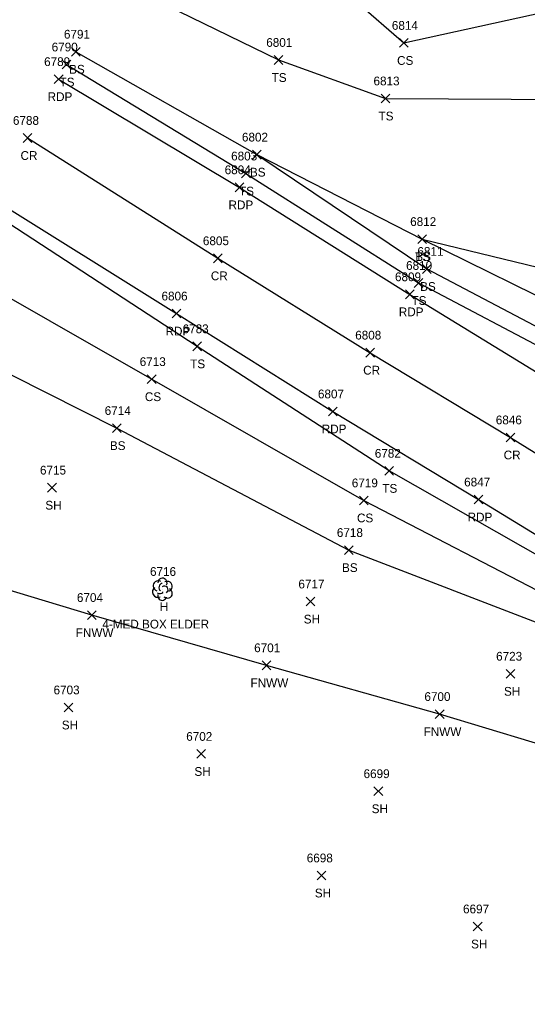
# Model space of a CAD drawing. Extents: x 1505656 to 1508446, y 700805 to 703031.
# Drawn here: x 1507222.6 to 1507338.7, y 701219.6 to 701441 of the extents above; entities that cross this region are included whole.
import ezdxf

# ---------------------------------------------------------------- set-up
doc = ezdxf.new("R2010")
doc.units = 0
for name, color, linetype in [('L_A', 7, 'Continuous'), ('L_C', 7, 'Continuous'), ('L_I', 7, 'Continuous'), ('L_TIC', 7, 'Continuous'), ('LELB', 7, 'Continuous'), ('LFNC', 7, 'Continuous'), ('LTD', 7, 'Continuous'), ('P_A', 7, 'Continuous'), ('P_I', 7, 'Continuous'), ('P_TIC', 7, 'Continuous'), ('PET', 7, 'Continuous'), ('PRC', 7, 'Continuous')]:
    doc.layers.add(name, color=color, linetype=linetype)

msp = doc.modelspace()

# ---------------------------------------------------------------- linework, layer by layer
at = {"layer": 'L_TIC'}
for points in [[(1507309.43, 701434.66), (1507311.43, 701436.66)], [(1507311.43, 701434.66), (1507309.43, 701436.66)], [(1507234.56, 701432.65), (1507236.56, 701434.65)], [(1507236.56, 701432.65), (1507234.56, 701434.65)], [(1507280.83, 701430.77), (1507282.83, 701432.77)], [(1507282.83, 701430.77), (1507280.83, 701432.77)], [(1507232.42, 701429.73), (1507234.42, 701431.73)], [(1507234.42, 701429.73), (1507232.42, 701431.73)], [(1507305.24, 701421.98), (1507307.24, 701423.98)], [(1507307.24, 701421.98), (1507305.24, 701423.98)], [(1507275.85, 701409.17), (1507277.85, 701411.17)], [(1507277.85, 701409.17), (1507275.85, 701411.17)], [(1507275.85, 701409.17), (1507277.85, 701411.17)], [(1507277.85, 701409.17), (1507275.85, 701411.17)], [(1507273.38, 701404.85), (1507275.38, 701406.85)], [(1507275.38, 701404.85), (1507273.38, 701406.85)], [(1507313.61, 701389.89), (1507315.61, 701391.89)], [(1507315.61, 701389.89), (1507313.61, 701391.89)], [(1507313.61, 701389.89), (1507315.61, 701391.89)], [(1507315.61, 701389.89), (1507313.61, 701391.89)], [(1507314.69, 701383.08), (1507316.69, 701385.08)], [(1507316.69, 701383.08), (1507314.69, 701385.08)], [(1507312.77, 701379.88), (1507314.77, 701381.88)], [(1507314.77, 701379.88), (1507312.77, 701381.88)], [(1507262.23, 701365.42), (1507264.23, 701367.42)], [(1507264.23, 701365.42), (1507262.23, 701367.42)], [(1507251.86, 701357.93), (1507253.86, 701359.93)], [(1507253.86, 701357.93), (1507251.86, 701359.93)], [(1507243.87, 701346.76), (1507245.87, 701348.76)], [(1507245.87, 701346.76), (1507243.87, 701348.76)], [(1507306.1, 701337.01), (1507308.1, 701339.01)], [(1507308.1, 701337.01), (1507306.1, 701339.01)], [(1507229.09, 701333.17), (1507231.09, 701335.17)], [(1507231.09, 701333.17), (1507229.09, 701335.17)], [(1507300.28, 701330.26), (1507302.28, 701332.26)], [(1507302.28, 701330.26), (1507300.28, 701332.26)], [(1507296.87, 701318.93), (1507298.87, 701320.93)], [(1507298.87, 701318.93), (1507296.87, 701320.93)], [(1507288.09, 701307.18), (1507290.09, 701309.18)], [(1507290.09, 701307.18), (1507288.09, 701309.18)], [(1507238.17, 701304.1), (1507240.17, 701306.1)], [(1507240.17, 701304.1), (1507238.17, 701306.1)], [(1507278.07, 701292.63), (1507280.07, 701294.63)], [(1507280.07, 701292.63), (1507278.07, 701294.63)], [(1507333.8, 701290.7), (1507335.8, 701292.7)], [(1507335.8, 701290.7), (1507333.8, 701292.7)], [(1507232.84, 701283.01), (1507234.84, 701285.01)], [(1507234.84, 701283.01), (1507232.84, 701285.01)], [(1507317.6, 701281.5), (1507319.6, 701283.5)], [(1507319.6, 701281.5), (1507317.6, 701283.5)], [(1507263.13, 701272.41), (1507265.13, 701274.41)], [(1507265.13, 701272.41), (1507263.13, 701274.41)], [(1507303.6, 701263.9), (1507305.6, 701265.9)], [(1507305.6, 701263.9), (1507303.6, 701265.9)], [(1507290.61, 701244.67), (1507292.61, 701246.67)], [(1507292.61, 701244.67), (1507290.61, 701246.67)], [(1507326.29, 701233.03), (1507328.29, 701235.03)], [(1507328.29, 701233.03), (1507326.29, 701235.03)]]:
    msp.add_lwpolyline(points, dxfattribs=at)
at = {"layer": 'LELB'}
for points in [[(1507253.51, 701468.63), (1507288.66, 701454.6), (1507310.43, 701435.66), (1507348.27, 701444), (1507370.84, 701446.3), (1507401.59, 701448.68)], [(1507244.77, 701449.89), (1507281.83, 701431.77), (1507306.24, 701422.98), (1507349.34, 701422.75), (1507389.23, 701429.14), (1507420.95, 701414.98), (1507446.82, 701397.27), (1507479.15, 701378.11), (1507493.85, 701367.81), (1507514.9, 701342.52), (1507491.37, 701327.79), (1507458.66, 701337.87), (1507423.97, 701348.78), (1507386.76, 701365.39), (1507354.41, 701381.26)], [(1507235.56, 701433.65), (1507276.85, 701410.17), (1507315.69, 701384.08), (1507347.33, 701367.45), (1507378.23, 701346.54), (1507406.05, 701333.56), (1507432.55, 701320.24), (1507465.52, 701310.91), (1507482.03, 701304.93), (1507508.08, 701304.28), (1507527, 701309.32), (1507530.54, 701311.37), (1507534.33, 701313.25), (1507542.53, 701316.02)], [(1507233.42, 701430.73), (1507274.38, 701405.85), (1507313.77, 701380.88), (1507345.78, 701364.01), (1507376.65, 701344.28), (1507403.21, 701328.51), (1507429.39, 701315.22), (1507462.05, 701305), (1507481.51, 701300.2), (1507509.4, 701297.47), (1507533.93, 701303.18), (1507548.93, 701313.82)], [(1507276.85, 701410.17), (1507314.61, 701390.89), (1507350.47, 701373.21), (1507382.29, 701350.94), (1507409.06, 701339.05), (1507436.21, 701326.88), (1507468.39, 701316.49), (1507482.66, 701312.29), (1507508.07, 701310.82), (1507524.68, 701314.62), (1507530.84, 701315.71), (1507533.71, 701315.69), (1507538.02, 701318.49)], [(1507664.64, 701288.76), (1507647.23, 701299.02), (1507624.46, 701303.4), (1507602.75, 701298.73), (1507589.52, 701290.79), (1507567.73, 701274.99), (1507546.1, 701263.56), (1507532.57, 701260.5), (1507511.15, 701257.25), (1507494.82, 701257.14), (1507477.93, 701258.45), (1507454.88, 701263), (1507442.63, 701266.73), (1507416.76, 701276.5), (1507380.5, 701295.43), (1507349.66, 701313.74), (1507307.1, 701338.01), (1507263.23, 701366.42), (1507214.44, 701398.2)], [(1507314.61, 701390.89), (1507354.41, 701381.26)], [(1507206.22, 701385.53), (1507252.86, 701358.93), (1507301.28, 701331.26), (1507345.08, 701308.55), (1507379.28, 701292.34), (1507415.34, 701274.6), (1507442.69, 701262.41), (1507477.36, 701252.75), (1507504.09, 701250.04), (1507524.24, 701244.68), (1507543.71, 701240.05), (1507564.82, 701236.64), (1507598.94, 701231.93), (1507652.74, 701217.67)], [(1507196.76, 701372), (1507244.87, 701347.76), (1507297.87, 701319.93), (1507344.77, 701301.89), (1507376.8, 701287.99), (1507414.57, 701272.26), (1507441.62, 701260.06), (1507475.85, 701242.93), (1507502.94, 701235.06), (1507524.76, 701229.88), (1507541.19, 701229.88), (1507544.67, 701227.39), (1507563.69, 701226.67), (1507597.85, 701222.6), (1507649.46, 701209.48)]]:
    msp.add_lwpolyline(points, dxfattribs=at)
at = {"layer": 'LFNC'}
msp.add_lwpolyline([(1507721.58, 701162.07), (1507708.46, 701169.26), (1507682.76, 701176.46), (1507629.63, 701192.11), (1507592.19, 701203.04), (1507562.07, 701211.89), (1507541.96, 701217.44), (1507530.4, 701220.69), (1507490.47, 701232.17), (1507463.39, 701240.21), (1507439.34, 701246.9), (1507401.64, 701257.79), (1507360.86, 701269.69), (1507318.6, 701282.5), (1507279.07, 701293.63), (1507239.17, 701305.1), (1507200.8, 701316.65)], dxfattribs=at)
at = {"layer": 'LTD'}
msp.add_line((1507255.27, 701311.04), (1507255.27, 701311.04), dxfattribs=at)
msp.add_line((1507255.27, 701311.04), (1507255.27, 701311.04), dxfattribs=at)
msp.add_arc((1507255.31, 701312.47), 1.05, 335.5272, 180.9563, dxfattribs=at)
for centre, major_axis, ratio, start_param, end_param in [((1507254.48, 701311.7), (1.21, -0.51), 0.895232, 1.570796, 4.712389), ((1507256.31, 701311.62), (-1.14, -0.48), 0.949671, 1.570796, 4.712389), ((1507254.18, 701310.33), (0.58, -1.04), 0.959034, 3.141593, 6.283185), ((1507254.81, 701310.29), (-0.625, -0.083), 0.423636, 0, 3.141593), ((1507255.06, 701311.5), (-0.208, -0.792), 0.645439, 3.141593, 6.283185), ((1507255.77, 701310.87), (-0.5, 0.667), 0.989748, 3.141593, 6.283185), ((1507256.27, 701310.2), (-1.09, 0.79), 0.841452, 1.570796, 4.712389), ((1507255.27, 701309.54), (0.26, 1.06), 0.942809, 1.570796, 4.712389)]:
    msp.add_ellipse(centre, major_axis=major_axis, ratio=ratio, start_param=start_param, end_param=end_param, dxfattribs=at)
at = {"layer": 'P_TIC'}
for points in [[(1507230.61, 701426.39), (1507232.61, 701428.39)], [(1507232.61, 701426.39), (1507230.61, 701428.39)], [(1507223.48, 701412.97), (1507225.48, 701414.97)], [(1507225.48, 701412.97), (1507223.48, 701414.97)], [(1507271.91, 701401.71), (1507273.91, 701403.71)], [(1507273.91, 701401.71), (1507271.91, 701403.71)], [(1507266.93, 701385.51), (1507268.93, 701387.51)], [(1507268.93, 701385.51), (1507266.93, 701387.51)], [(1507310.8, 701377.29), (1507312.8, 701379.29)], [(1507312.8, 701377.29), (1507310.8, 701379.29)], [(1507257.54, 701372.9), (1507259.54, 701374.9)], [(1507259.54, 701372.9), (1507257.54, 701374.9)], [(1507301.71, 701363.98), (1507303.71, 701365.98)], [(1507303.71, 701363.98), (1507301.71, 701365.98)], [(1507293.19, 701350.56), (1507295.19, 701352.56)], [(1507295.19, 701350.56), (1507293.19, 701352.56)], [(1507333.78, 701344.63), (1507335.78, 701346.63)], [(1507335.78, 701344.63), (1507333.78, 701346.63)], [(1507326.49, 701330.46), (1507328.49, 701332.46)], [(1507328.49, 701330.46), (1507326.49, 701332.46)]]:
    msp.add_lwpolyline(points, dxfattribs=at)
at = {"layer": 'PET'}
for points in [[(1507231.61, 701427.39), (1507272.91, 701402.71), (1507311.8, 701378.29), (1507343.21, 701359.04), (1507374.88, 701340.26), (1507401.32, 701325.13), (1507427.17, 701310.75), (1507459.87, 701298.7), (1507480.09, 701294.48), (1507509.29, 701293.36), (1507525.83, 701296.14), (1507540.02, 701301.61), (1507551.73, 701310.36)], [(1507215.48, 701400.74), (1507258.54, 701373.9), (1507294.19, 701351.56), (1507327.49, 701331.46), (1507359.99, 701311.61), (1507385.1, 701296.57), (1507413.33, 701281.68), (1507446.05, 701268.76), (1507474.38, 701261.9), (1507510.64, 701260.64), (1507538.44, 701265.38), (1507556.26, 701273.11), (1507573.81, 701284.3)]]:
    msp.add_lwpolyline(points, dxfattribs=at)
at = {"layer": 'PRC'}
msp.add_lwpolyline([(1507224.48, 701413.97), (1507267.93, 701386.51), (1507302.71, 701364.98), (1507334.78, 701345.63), (1507366.2, 701326.16), (1507393.17, 701310.52), (1507419.83, 701295.27), (1507450.97, 701283.62), (1507477.64, 701277.69), (1507509.18, 701276.82), (1507530.27, 701280.07), (1507548.96, 701287.59), (1507564.92, 701299.3)], dxfattribs=at)

# ---------------------------------------------------------------- texts
at = {"layer": 'L_A'}
for s, p in [('CS', (1507308.88, 701430.66)), ('BS', (1507234, 701428.65)), ('TS', (1507231.82, 701425.73)), ('TS', (1507280.24, 701426.77)), ('TS', (1507304.65, 701417.98)), ('BS', (1507275.29, 701405.17)), ('BS', (1507275.29, 701405.17)), ('TS', (1507272.79, 701400.85)), ('TS', (1507313.01, 701385.89)), ('BS', (1507313.05, 701385.89)), ('BS', (1507314.14, 701379.08)), ('TS', (1507312.18, 701375.88)), ('TS', (1507261.64, 701361.42)), ('CS', (1507251.3, 701353.93)), ('BS', (1507243.31, 701342.76)), ('TS', (1507305.51, 701333.01)), ('SH', (1507228.57, 701329.17)), ('CS', (1507299.73, 701326.26)), ('BS', (1507296.31, 701314.93)), ('H', (1507254.7, 701306.04)), ('SH', (1507287.57, 701303.18)), ('FNWW', (1507235.52, 701300.1)), ('FNWW', (1507275.42, 701288.63)), ('SH', (1507333.28, 701286.7)), ('SH', (1507232.33, 701279.01)), ('FNWW', (1507314.94, 701277.5)), ('SH', (1507262.61, 701268.41)), ('SH', (1507303.08, 701259.9)), ('SH', (1507290.1, 701240.67)), ('SH', (1507325.78, 701229.03))]:
    msp.add_text(s, height=2, dxfattribs=at).set_placement(p)
at = {"layer": 'L_C'}
msp.add_text('4-MED BOX ELDER', height=2, dxfattribs=at).set_placement((1507241.59, 701302.04))
at = {"layer": 'L_I'}
for s, p in [('6814', (1507307.69, 701438.66)), ('6791', (1507232.82, 701436.65)), ('6801', (1507279.01, 701434.77)), ('6790', (1507230.02, 701433.73)), ('6813', (1507303.5, 701425.98)), ('6802', (1507273.46, 701413.17)), ('6802', (1507273.46, 701413.17)), ('6803', (1507270.99, 701408.85)), ('6812', (1507311.87, 701393.89)), ('6812', (1507311.87, 701393.89)), ('6811', (1507313.52, 701387.08)), ('6810', (1507310.94, 701383.88)), ('6783', (1507259.92, 701369.42)), ('6713', (1507250.12, 701361.93)), ('6714', (1507242.13, 701350.76)), ('6782', (1507303.79, 701341.01)), ('6715', (1507227.35, 701337.17)), ('6719', (1507298.54, 701334.26)), ('6718', (1507295.13, 701322.93)), ('6716', (1507252.47, 701314.04)), ('6717', (1507286.35, 701311.18)), ('6704', (1507235.78, 701308.1)), ('6701', (1507276.25, 701296.63)), ('6723', (1507331.49, 701294.7)), ('6703', (1507230.45, 701287.01)), ('6700', (1507315.12, 701285.5)), ('6702', (1507260.74, 701276.41)), ('6699', (1507301.23, 701267.9)), ('6698', (1507288.26, 701248.67)), ('6697', (1507323.94, 701237.03))]:
    msp.add_text(s, height=2, dxfattribs=at).set_placement(p)
at = {"layer": 'P_A'}
for s, p in [('RDP', (1507229.09, 701422.39)), ('CR', (1507222.91, 701408.97)), ('RDP', (1507270.4, 701397.71)), ('CR', (1507266.36, 701381.51)), ('RDP', (1507309.28, 701373.29)), ('RDP', (1507256.02, 701368.9)), ('CR', (1507301.14, 701359.98)), ('RDP', (1507291.68, 701346.56)), ('CR', (1507333.22, 701340.63)), ('RDP', (1507324.98, 701326.46))]:
    msp.add_text(s, height=2, dxfattribs=at).set_placement(p)
at = {"layer": 'P_I'}
for s, p in [('6789', (1507228.29, 701430.39)), ('6788', (1507221.17, 701416.97)), ('6804', (1507269.52, 701405.71)), ('6805', (1507264.54, 701389.51)), ('6809', (1507308.4, 701381.29)), ('6806', (1507255.1, 701376.9)), ('6808', (1507299.32, 701367.98)), ('6807', (1507290.81, 701354.56)), ('6846', (1507331.42, 701348.63)), ('6847', (1507324.19, 701334.46))]:
    msp.add_text(s, height=2, dxfattribs=at).set_placement(p)

doc.saveas('drawing.dxf')
